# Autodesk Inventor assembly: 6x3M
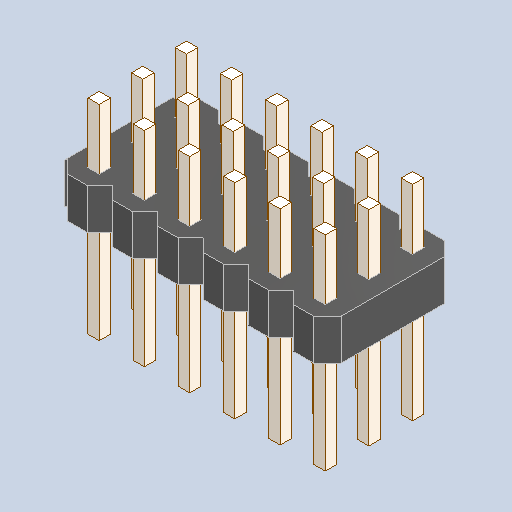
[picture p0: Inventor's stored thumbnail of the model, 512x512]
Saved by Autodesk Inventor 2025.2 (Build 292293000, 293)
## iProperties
Created: 2025-04
Part Number: 6x3M
Description: PART--DESC
Document SubType Name: Assembly
Designer: BennF
Author: BennF
Revision Number: NONE
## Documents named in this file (3)
- C:\Users\BennF\Nextcloud\Benutzer\CNC JarBeRi\existing parts\Electronics\RepRap A4988 Shied (USE WITHOUT ARDUINO)\reprap-a4988-1.snapshot.1\RepRap\RepRap\6x3M.iam
- C:\Users\BennF\Nextcloud\Benutzer\CNC JarBeRi\existing parts\Electronics\RepRap A4988 Shied (USE WITHOUT ARDUINO)\reprap-a4988-1.snapshot.1\RepRap\RepRap\6x3M Geometry.ipt
- C:\Users\BennF\Nextcloud\Benutzer\CNC JarBeRi\existing parts\Electronics\RepRap A4988 Shied (USE WITHOUT ARDUINO)\reprap-a4988-1.snapshot.1\RepRap\RepRap\pin2.ipt
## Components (2 placed, 2 different names)
1. 6x3M Geometry
2. pin2
